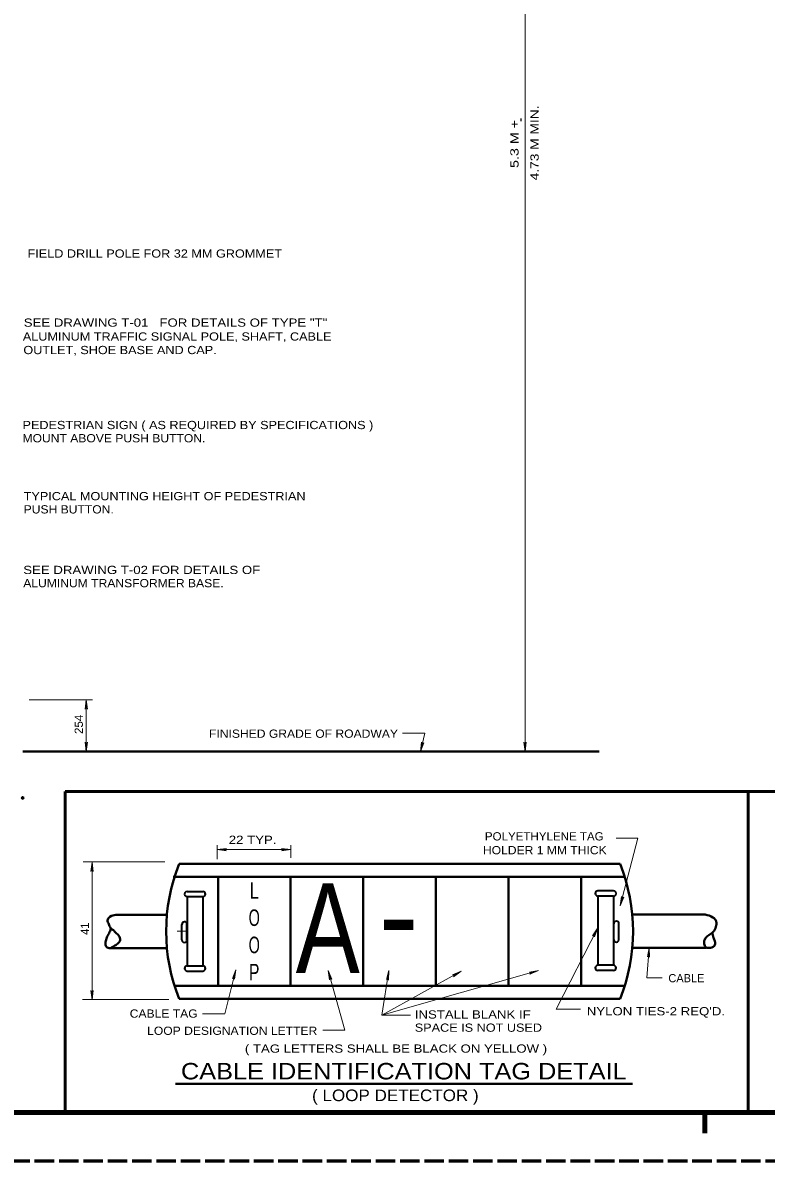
# Model space of a CAD drawing. Extents: x 312583 to 312853, y 144419 to 144586.
# Drawn here: x 312664.4 to 312733, y 144418.6 to 144523.7 of the extents above; entities that cross this region are included whole.
import ezdxf
from ezdxf.enums import TextEntityAlignment as Align

# ---------------------------------------------------------------- set-up
doc = ezdxf.new("R2010")
doc.units = 0
doc.header["$LTSCALE"] = 0.3
doc.header["$PDMODE"] = 32
doc.header["$PDSIZE"] = 0.15
doc.linetypes.add('LONG_DASHED', pattern=[7.5, 6, -1.5])
for name, color, linetype, lineweight in [('1', 7, 'Continuous', 40), ('2', 7, 'Continuous', 13), ('63', 7, 'LONG_DASHED', 60)]:
    doc.layers.add(name, color=color, linetype=linetype, lineweight=lineweight)

msp = doc.modelspace()

# ---------------------------------------------------------------- linework, layer by layer
at = {"layer": '1'}
for p, q in [((312664.3438, 144456.4179), (312717.6041, 144456.4179)), ((312678.7919, 144446.0449), (312719.5249, 144446.0449)), ((312682.3876, 144434.7826), (312682.3876, 144444.8489)), ((312689.0959, 144434.7826), (312689.0959, 144444.8489)), ((312695.8042, 144434.7826), (312695.8042, 144444.8489)), ((312702.5126, 144434.7826), (312702.5126, 144444.8489)), ((312702.5126, 144434.7826), (312702.5126, 144444.8489)), ((312709.2209, 144434.7826), (312709.2209, 144444.8489)), ((312715.9292, 144434.7826), (312715.9292, 144444.8489)), ((312672.9499, 144441.3453), (312675.1426, 144441.3453)), ((312720.7132, 144441.3759), (312727.3986, 144441.3759)), ((312720.7132, 144438.3093), (312727.5059, 144438.3093)), ((312678.7919, 144433.5866), (312719.5249, 144433.5866)), ((312678.4492, 144425.7451), (312720.6737, 144425.7451))]:
    msp.add_line(p, q, dxfattribs=at)
at = {"layer": '1', "lineweight": 53}
for p, q in [((312668.2732, 144423.0846), (312668.2732, 144452.7259)), ((312803.31, 144452.7259), (312668.2732, 144452.7259)), ((312731.3479, 144423.0846), (312731.3479, 144452.7259))]:
    msp.add_line(p, q, dxfattribs=at)
at = {"layer": '1', "lineweight": 13}
for p, q in [((312682.3186, 144446.4819), (312682.3186, 144447.7776)), ((312689.1189, 144446.5969), (312689.1189, 144447.7776)), ((312719.1569, 144448.4293), (312721.1579, 144448.4293)), ((312682.3186, 144447.3713), (312689.1036, 144447.3713)), ((312669.9216, 144446.2289), (312677.4732, 144446.2289)), ((312670.7572, 144433.4869), (312670.7572, 144446.1983)), ((312697.5292, 144432.0839), (312712.0039, 144436.1933)), ((312722.0089, 144435.5109), (312723.4042, 144435.5109)), ((312669.8602, 144433.5176), (312677.8412, 144433.5176)), ((312680.9386, 144432.1913), (312683.0086, 144432.1913)), ((312697.5292, 144432.0839), (312700.1589, 144432.0839)), ((312713.6292, 144432.6436), (312715.8832, 144432.6436)), ((312692.0782, 144430.7039), (312694.0869, 144430.7039))]:
    msp.add_line(p, q, dxfattribs=at)
at = {"layer": '1', "lineweight": 35}
for p, q in [((312679.5432, 144443.4996), (312680.9846, 144443.4996)), ((312718.9192, 144443.5533), (312717.4779, 144443.5533)), ((312679.5432, 144443.0243), (312680.9846, 144443.0243)), ((312718.9192, 144443.0779), (312717.4779, 144443.0779)), ((312679.0449, 144439.0223), (312679.0449, 144440.4636)), ((312679.5202, 144439.0223), (312679.5202, 144440.4636)), ((312718.9422, 144439.0759), (312718.9422, 144440.5173)), ((312719.4176, 144439.0759), (312719.4176, 144440.5173)), ((312679.5432, 144436.6303), (312680.9846, 144436.6303)), ((312679.5432, 144436.1473), (312680.9846, 144436.1473)), ((312718.9192, 144436.6839), (312717.4779, 144436.6839)), ((312718.9192, 144436.2009), (312717.4779, 144436.2009))]:
    msp.add_line(p, q, dxfattribs=at)
at = {"layer": '1', "lineweight": 158}
for p, q in [((312616.5, 144423.0846), (312849, 144423.0846)), ((312727.35, 144421.1646), (312727.35, 144423.0846))]:
    msp.add_line(p, q, dxfattribs=at)
at = {"layer": '1'}
for points in [[(312678.2552, 144444.8489), (312702.5126, 144444.8489), (312719.8546, 144444.8489)], [(312675.1426, 144441.3453), (312676.1546, 144441.3453), (312677.6726, 144441.3453)], [(312672.3519, 144438.2786), (312675.1426, 144438.2786), (312676.4766, 144438.2786), (312677.6726, 144438.2786)], [(312678.3089, 144434.7826), (312702.5126, 144434.7826), (312719.9082, 144434.7826)]]:
    msp.add_lwpolyline(points, dxfattribs=at)
at = {"layer": '1', "lineweight": 35}
for points in [[(312679.5432, 144443.0243), (312679.5432, 144438.1713), (312679.5432, 144436.6303)], [(312680.9846, 144443.0243), (312680.9846, 144438.1713), (312680.9846, 144436.6303)], [(312717.4779, 144443.0779), (312717.4779, 144438.1713), (312717.4779, 144436.6839)], [(312718.9192, 144443.0779), (312718.9192, 144438.1713), (312718.9192, 144436.6839)]]:
    msp.add_lwpolyline(points, dxfattribs=at)
for centre, radius, start, end in [((312679.5351, 144443.262), 0.2377, 88.05031, 270.1016), ((312680.9846, 144443.2619), 0.2377, 271.83343, 90.01466), ((312717.4778, 144443.3155), 0.2377, 89.98534, 268.16657), ((312718.9273, 144443.3157), 0.2377, 269.8984, 91.94969), ((312679.2826, 144440.4637), 0.2377, 1.83342, 180.01466), ((312719.1798, 144440.5173), 0.2377, 359.98534, 178.16657), ((312679.2825, 144439.0142), 0.2377, 178.05031, 0.1016), ((312719.18, 144439.0678), 0.2377, 179.8984, 1.94969), ((312679.5471, 144436.3888), 0.2415, 90.90938, 269.09062), ((312680.981, 144436.3888), 0.2415, 270.85072, 89.14928), ((312717.4815, 144436.4424), 0.2415, 90.85072, 269.14928), ((312718.9154, 144436.4424), 0.2415, 270.90938, 89.09062)]:
    msp.add_arc(centre, radius, start, end, dxfattribs=at)
at = {"layer": '1'}
for points in [[(312672.9499, 144441.3453), (312672.4056, 144441.1689), (312672.1756, 144440.8316), (312672.2982, 144440.4943), (312672.4669, 144440.1339), (312672.7276, 144439.9193), (312672.9422, 144439.6739), (312673.2336, 144439.4133), (312673.3409, 144438.9993), (312673.0956, 144438.6619), (312672.7736, 144438.4473), (312672.3289, 144438.2709), (312672.0222, 144438.4779), (312672.0222, 144438.9379), (312672.1449, 144439.3366), (312672.3749, 144439.7659), (312672.4976, 144440.0879)], [(312727.3986, 144441.3759), (312728.1039, 144441.0999), (312728.4106, 144440.7319), (312728.3799, 144440.2413), (312728.1346, 144439.7813), (312727.7359, 144439.4746), (312727.3986, 144439.1679), (312727.3066, 144438.6773), (312727.4906, 144438.3399), (312727.7206, 144438.3016), (312728.2266, 144438.4626), (312728.2879, 144438.9226), (312728.1652, 144439.2293), (312728.0579, 144439.7046)]]:
    msp.add_spline(points, degree=3, dxfattribs=at)
msp.add_point((312664.3438, 144452.1476), dxfattribs=at)
at = {"layer": '2'}
for p, q in [((312710.7501, 144456.4179), (312710.7501, 144555.2949)), ((312670.8068, 144461.2096), (312664.9418, 144461.2096)), ((312670.2088, 144461.2096), (312670.1014, 144460.3433)), ((312670.2088, 144456.4179), (312670.2088, 144461.2096)), ((312670.2088, 144461.2096), (312670.3161, 144460.3433)), ((312670.1014, 144460.3433), (312670.2088, 144460.6193)), ((312670.3161, 144460.3433), (312670.2088, 144460.6193)), ((312701.4964, 144458.1276), (312699.4264, 144458.1276)), ((312701.0978, 144456.4179), (312701.4964, 144458.1276)), ((312670.1014, 144457.2843), (312670.2088, 144457.0083)), ((312670.2088, 144456.4179), (312670.1014, 144457.2843)), ((312670.3161, 144457.2843), (312670.2088, 144457.0083)), ((312670.2088, 144456.4179), (312670.3161, 144457.2843)), ((312701.0978, 144456.4179), (312701.1898, 144457.2919)), ((312701.0978, 144456.4179), (312701.3968, 144457.2383)), ((312701.1898, 144457.2919), (312701.2281, 144456.9929)), ((312701.3968, 144457.2383), (312701.2281, 144456.9929)), ((312710.6428, 144457.2843), (312710.7501, 144457.0083)), ((312710.7501, 144456.4179), (312710.6428, 144457.2843)), ((312710.8574, 144457.2843), (312710.7501, 144457.0083)), ((312710.7501, 144456.4179), (312710.8574, 144457.2843)), ((312721.1579, 144448.4293), (312719.5479, 144442.1656)), ((312682.3186, 144447.3713), (312683.1849, 144447.4786)), ((312682.3186, 144447.3713), (312683.1849, 144447.2639)), ((312683.1849, 144447.4786), (312682.9089, 144447.3713)), ((312683.1849, 144447.2639), (312682.9089, 144447.3713)), ((312688.2372, 144447.4786), (312688.5132, 144447.3713)), ((312689.1036, 144447.3713), (312688.2372, 144447.4786)), ((312688.2372, 144447.2639), (312688.5132, 144447.3713)), ((312689.1036, 144447.3713), (312688.2372, 144447.2639)), ((312670.7572, 144446.1983), (312670.6499, 144445.3319)), ((312670.6499, 144445.3319), (312670.7572, 144445.6079)), ((312670.7572, 144446.1983), (312670.8646, 144445.3319)), ((312670.8646, 144445.3319), (312670.7572, 144445.6079)), ((312719.5479, 144442.1656), (312719.6629, 144443.0319)), ((312719.5479, 144442.1656), (312719.8699, 144442.9783)), ((312719.6629, 144443.0319), (312719.6936, 144442.7406)), ((312719.8699, 144442.9783), (312719.6936, 144442.7406)), ((312679.3822, 144439.8273), (312678.6156, 144439.8273)), ((312717.4779, 144440.1339), (312713.6292, 144432.6436)), ((312717.4779, 144440.1339), (312716.9872, 144439.4133)), ((312716.9872, 144439.4133), (312717.2096, 144439.6126)), ((312717.4779, 144440.1339), (312717.1789, 144439.3136)), ((312717.1789, 144439.3136), (312717.2096, 144439.6126)), ((312722.0089, 144435.5109), (312722.2159, 144438.3093)), ((312722.2159, 144438.3093), (312722.0472, 144437.4506)), ((312722.2159, 144438.3093), (312722.2466, 144437.4429)), ((312722.0472, 144437.4506), (312722.1546, 144437.7266)), ((312722.2466, 144437.4429), (312722.1546, 144437.7266)), ((312683.0086, 144432.1913), (312684.0282, 144436.2699)), ((312684.0282, 144436.2699), (312683.7139, 144435.4573)), ((312684.0282, 144436.2699), (312683.9209, 144435.4036)), ((312694.0869, 144430.7039), (312692.5612, 144436.1933)), ((312692.5612, 144436.1933), (312692.6916, 144435.3269)), ((312692.5612, 144436.1933), (312692.8986, 144435.3883)), ((312697.5292, 144432.0839), (312698.1809, 144436.1933)), ((312697.5292, 144432.0839), (312704.8586, 144436.1319)), ((312698.1809, 144436.1933), (312697.9356, 144435.3576)), ((312698.1809, 144436.1933), (312698.1502, 144435.3193)), ((312704.8586, 144436.1319), (312704.0459, 144435.8099)), ((312704.8586, 144436.1319), (312704.1532, 144435.6183)), ((312712.0039, 144436.1933), (312711.1452, 144436.0629)), ((312711.1452, 144436.0629), (312711.4366, 144436.0323)), ((312712.0039, 144436.1933), (312711.1989, 144435.8559)), ((312711.1989, 144435.8559), (312711.4366, 144436.0323)), ((312683.7139, 144435.4573), (312683.8826, 144435.6949)), ((312683.9209, 144435.4036), (312683.8826, 144435.6949)), ((312692.6916, 144435.3269), (312692.7222, 144435.6259)), ((312692.8986, 144435.3883), (312692.7222, 144435.6259)), ((312697.9356, 144435.3576), (312698.0889, 144435.6106)), ((312698.1502, 144435.3193), (312698.0889, 144435.6106)), ((312704.0459, 144435.8099), (312704.3449, 144435.8483)), ((312704.1532, 144435.6183), (312704.3449, 144435.8483)), ((312670.6499, 144434.3533), (312670.7572, 144434.0773)), ((312670.7572, 144433.4869), (312670.6499, 144434.3533)), ((312670.8646, 144434.3533), (312670.7572, 144434.0773)), ((312670.7572, 144433.4869), (312670.8646, 144434.3533))]:
    msp.add_line(p, q, dxfattribs=at)
at = {"layer": '2', "lineweight": 40}
for centre, start, end in [((312694.4157, 144439.8158), 158.26294, 201.73706), ((312703.9011, 144439.8158), 338.26294, 21.73706)]:
    msp.add_arc(centre, 16.8198, start, end, dxfattribs=at)
at = {"layer": '63'}
msp.add_line((312851.75, 144418.5846), (312583.526, 144418.5846), dxfattribs=at)

# ---------------------------------------------------------------- texts
at = {"layer": '2'}
for s, width, p in [('4.73 M MIN.', 1.25, (312712.0055, 144509.1871)), ('5.3 M +', 1.3, (312710.149, 144510.33)), ('254', 1.05, (312669.9033, 144458.0458))]:
    msp.add_text(s, height=0.76, rotation=90, dxfattribs=dict(at, width=width)).set_placement(p)
msp.add_text('-', height=0.92, rotation=90, dxfattribs=at).set_placement((312710.7348, 144514.7766), align=Align.CENTER)
for s, width, p in [('FIELD DRILL POLE FOR 32 MM GROMMET', 1.15, (312664.7923, 144502.049)), ('SEE DRAWING T-01   FOR DETAILS OF TYPE "T"', 1.2, (312664.4413, 144495.6685)), ('ALUMINUM TRAFFIC SIGNAL POLE, SHAFT, CABLE', 1.15, (312664.3576, 144494.3862)), ('OUTLET, SHOE BASE AND CAP.', 1.15, (312664.4078, 144493.1366)), ('PEDESTRIAN SIGN ( AS REQUIRED BY SPECIFICATIONS )', 1.15, (312664.3284, 144486.2096)), ('MOUNT ABOVE PUSH BUTTON.', 1.1, (312664.3284, 144484.9896)), ('TYPICAL MOUNTING HEIGHT OF PEDESTRIAN', 1.15, (312664.4358, 144479.6393)), ('PUSH BUTTON.', 1.1, (312664.4358, 144478.4193)), ('SEE DRAWING T-02 FOR DETAILS OF', 1.2, (312664.3974, 144472.8236)), ('ALUMINUM TRANSFORMER BASE.', 1.1, (312664.3974, 144471.6036)), ('FINISHED GRADE OF ROADWAY', 1.1, (312681.5573, 144457.6992)), ('22 TYP.', 1.2, (312683.3799, 144447.8954)), ('POLYETHYLENE TAG', 1.05, (312707.0382, 144448.2155)), ('HOLDER 1 MM THICK', 1.1, (312706.8582, 144446.9372)), ("NYLON TIES-2 REQ'D.", 1.2, (312716.4506, 144432.0581)), ('CABLE TAG', 1.1, (312674.2303, 144431.8434)), ('INSTALL BLANK IF', 1.2, (312700.5624, 144431.7638)), ('LOOP DESIGNATION LETTER', 1.1, (312675.8399, 144430.2574)), ('SPACE IS NOT USED', 1.15, (312700.5624, 144430.5438)), ('( TAG LETTERS SHALL BE BLACK ON YELLOW )', 1.2, (312684.8661, 144428.61))]:
    msp.add_text(s, height=0.76, dxfattribs=dict(at, width=width)).set_placement(p)
for s, height, width, p in [('L', 1.526, 0.75, (312685.7417, 144442.8326)), ('A', 8.28, 0.8, (312692.5229, 144435.9863)), ('O', 1.526, 0.65, (312685.7341, 144440.3179)), ('O', 1.526, 0.65, (312685.7341, 144437.8033)), ('P', 1.526, 0.7, (312685.7341, 144435.2886)), ('CABLE IDENTIFICATION TAG DETAIL', 1.52, 1.15, (312699.5487, 144426.1434)), ('( LOOP DETECTOR )', 1.07, 1.1, (312698.7695, 144424.137))]:
    msp.add_text(s, height=height, dxfattribs=dict(at, width=width)).set_placement(p, align=Align.CENTER)
msp.add_text('41 ', height=0.76, rotation=90, dxfattribs=at).set_placement((312670.4746, 144439.4976))
msp.add_text('-', height=8.28, dxfattribs=at).set_placement((312699.074, 144437.2206), align=Align.CENTER)
msp.add_text('CABLE', height=0.76, dxfattribs=at).set_placement((312723.9887, 144435.1151))

doc.saveas('drawing.dxf')
